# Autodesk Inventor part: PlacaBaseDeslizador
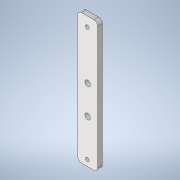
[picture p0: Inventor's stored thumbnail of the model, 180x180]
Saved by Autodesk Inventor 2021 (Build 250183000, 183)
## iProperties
Created: 2021-02
Part Number: PlacaBaseDeslizador
Material: Genérico
Document SubType Name: Modeling
Designer: ATOUZA
Density: 1 g/cm^3
Appearance: Valor por defecto
Author: ATOUZA
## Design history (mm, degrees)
node "Plano de trabajo1"
extrude "Extrusión1" new body sketch "Boceto1" distance "d8" = 5; taper "d9" = 0 deg
fillet "Empalme1" dims "d10" = 4
node "Sólido1"
other parameters: "d0" = 6, "d1" = 6, "d3" = 22.45, "d4" = 4, "d7" = 4
